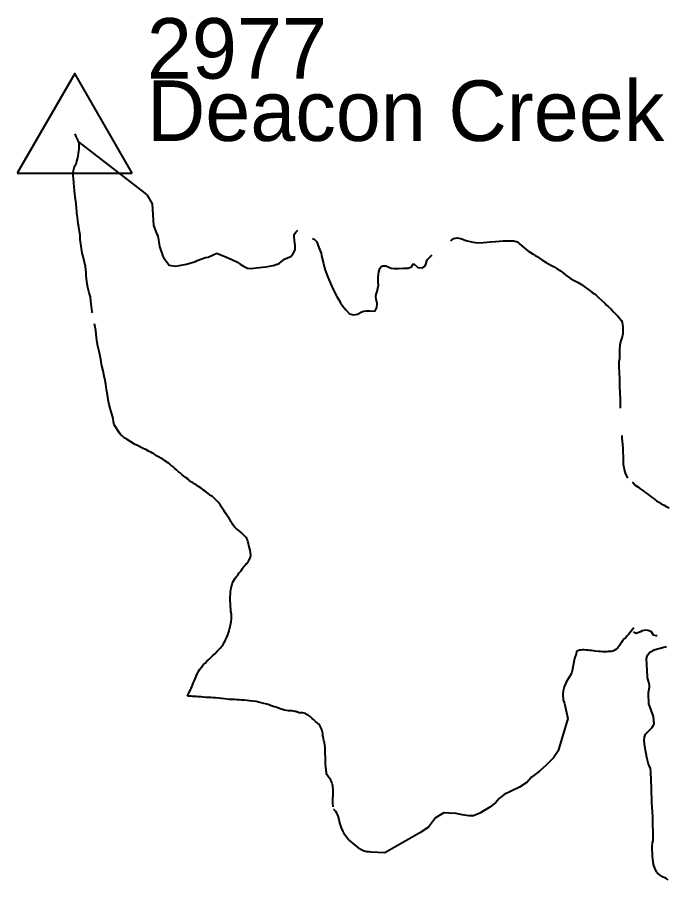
# Model space of a CAD drawing. Extents: x 322505 to 642419, y 5806860 to 5919753.
# Drawn here: x 548630 to 552397, y 5870230 to 5875217 of the extents above; entities that cross this region are included whole.
import ezdxf

# ---------------------------------------------------------------- set-up
doc = ezdxf.new("R2010")
doc.units = 0
doc.header["$LTSCALE"] = 140
doc.layers.add('1', color=7, linetype='Continuous', lineweight=40)
doc.layers.add('5', color=7, linetype='Continuous', lineweight=40)

msp = doc.modelspace()

# ---------------------------------------------------------------- linework, layer by layer
at = {"layer": '1'}
msp.add_line((548630.1, 5874315.4), (549295.5, 5874315.4), dxfattribs=at)
msp.add_lwpolyline([(549295.5, 5874315.4), (548962.8, 5874891.6), (548630.1, 5874315.4)], dxfattribs=at)
at = {"layer": '5'}
msp.add_line((548987, 5874494), (549368, 5874199), dxfattribs=at)
for points in [[(548960, 5874242), (548958, 5874254), (548957, 5874266), (548955, 5874283), (548954, 5874301), (548954, 5874317), (548955, 5874331), (548959, 5874346), (548963, 5874357), (548968, 5874366), (548972, 5874374), (548975, 5874385), (548978, 5874399), (548982, 5874414), (548985, 5874429), (548987, 5874443), (548988, 5874456), (548989, 5874470), (548989, 5874484), (548987, 5874494), (548981, 5874506), (548980, 5874509), (548974, 5874520), (548971, 5874527), (548965, 5874542)], [(548974, 5874094), (548973, 5874111), (548970, 5874140), (548967, 5874166), (548964, 5874194), (548962, 5874216), (548960, 5874238), (548960, 5874242)], [(549368, 5874199), (549382, 5874189), (549411, 5874139), (549418, 5874013), (549437, 5873962), (549443, 5873953), (549453, 5873891), (549471, 5873836), (549475, 5873828), (549509, 5873784), (549545, 5873777), (549608, 5873789), (549660, 5873805), (549670, 5873810), (549719, 5873827), (549734, 5873829), (549785, 5873852)], [(549065, 5873507), (549064, 5873513), (549060, 5873545), (549056, 5873576), (549053, 5873600), (549046, 5873624), (549038, 5873655), (549032, 5873688), (549030, 5873707), (549029, 5873724), (549028, 5873742), (549024, 5873776), (549018, 5873809), (549011, 5873833), (549006, 5873853), (549001, 5873879), (548997, 5873907), (548994, 5873932), (548993, 5873956), (548990, 5873979), (548987, 5874003), (548983, 5874025), (548980, 5874042), (548978, 5874061), (548975, 5874085), (548974, 5874094)], [(549785, 5873852), (549801, 5873845), (549817, 5873839), (549841, 5873829), (549871, 5873816), (549899, 5873802), (549919, 5873790), (549938, 5873777), (549961, 5873767), (549985, 5873765), (550012, 5873768), (550067, 5873773), (550110, 5873782), (550127, 5873787), (550144, 5873794), (550159, 5873805), (550176, 5873818), (550197, 5873827), (550212, 5873834), (550226, 5873850), (550237, 5873872), (550238, 5873896), (550233, 5873928), (550231, 5873948), (550232, 5873961), (550241, 5873975), (550253, 5873986)], [(551137, 5873925), (551141, 5873928), (551154, 5873938), (551173, 5873941), (551201, 5873936), (551223, 5873927), (551256, 5873918), (551292, 5873913), (551327, 5873914), (551367, 5873918), (551395, 5873921), (551419, 5873923), (551439, 5873924), (551463, 5873925), (551483, 5873925), (551501, 5873924), (551506, 5873923), (551516, 5873921)], [(550338, 5873938), (550347, 5873933), (550362, 5873918), (550371, 5873895), (550382, 5873867), (550387, 5873852), (550390, 5873837), (550400, 5873794), (550409, 5873761), (550422, 5873724), (550441, 5873677), (550459, 5873638), (550478, 5873603), (550489, 5873584), (550500, 5873566), (550513, 5873547), (550530, 5873525), (550551, 5873503), (550575, 5873496), (550597, 5873501), (550613, 5873508), (550619, 5873511), (550629, 5873516), (550632, 5873517), (550635, 5873517), (550651, 5873519), (550668, 5873520), (550689, 5873517), (550700, 5873519), (550704, 5873527), (550709, 5873538), (550711, 5873562), (550706, 5873586), (550704, 5873603), (550706, 5873616), (550711, 5873631), (550716, 5873651), (550718, 5873668), (550717, 5873685), (550717, 5873710), (550718, 5873729), (550720, 5873745), (550727, 5873765), (550734, 5873775), (550744, 5873780), (550762, 5873779), (550778, 5873771), (550792, 5873767), (550809, 5873765), (550835, 5873765), (550862, 5873766), (550891, 5873767), (550910, 5873774), (550919, 5873790), (550921, 5873794)], [(551516, 5873921), (551520, 5873918), (551534, 5873906), (551559, 5873886), (551583, 5873867), (551613, 5873848), (551625, 5873840), (551637, 5873833), (551645, 5873828), (551663, 5873815), (551689, 5873799), (551715, 5873783), (551734, 5873773), (551752, 5873762), (551771, 5873750), (551788, 5873737), (551803, 5873725), (551815, 5873716), (551830, 5873707), (551851, 5873695), (551873, 5873684), (551892, 5873672), (551909, 5873660), (551929, 5873645), (551943, 5873635), (551955, 5873626), (551965, 5873620), (551977, 5873610), (551992, 5873596), (552008, 5873581), (552027, 5873564), (552038, 5873553)], [(550921, 5873794), (550947, 5873770), (550970, 5873768), (550986, 5873778), (550994, 5873791), (550995, 5873794), (550995, 5873796), (551001, 5873815), (551019, 5873833), (551029, 5873841)], [(552038, 5873553), (552045, 5873547), (552064, 5873529), (552078, 5873514), (552092, 5873500), (552102, 5873489), (552115, 5873475), (552123, 5873466)], [(549223, 5872810), (549191, 5872860), (549187, 5872877), (549184, 5872897), (549177, 5872923), (549169, 5872949), (549162, 5872977), (549156, 5873004), (549151, 5873033), (549146, 5873065), (549142, 5873095), (549138, 5873117), (549133, 5873141), (549126, 5873173), (549118, 5873209), (549115, 5873225), (549113, 5873239), (549109, 5873257), (549103, 5873285), (549097, 5873315), (549093, 5873337), (549089, 5873366), (549084, 5873406), (549077, 5873445)], [(552123, 5873466), (552124, 5873463), (552128, 5873452), (552130, 5873440), (552131, 5873426), (552132, 5873413), (552132, 5873404), (552132, 5873397), (552131, 5873387), (552130, 5873376), (552125, 5873357), (552119, 5873340), (552114, 5873321), (552112, 5873297), (552112, 5873274), (552113, 5873255), (552112, 5873242), (552109, 5873224), (552108, 5873206), (552109, 5873188), (552110, 5873171), (552110, 5873169)], [(552110, 5873169), (552111, 5873152), (552112, 5873135), (552112, 5873120), (552112, 5873108), (552112, 5873094), (552113, 5873074), (552114, 5873053), (552115, 5873036), (552116, 5873021), (552116, 5873007), (552117, 5872995), (552117, 5872956)], [(549643, 5872527), (549636, 5872531), (549625, 5872539), (549622, 5872542), (549618, 5872544), (549615, 5872547), (549611, 5872551), (549606, 5872554), (549594, 5872564), (549582, 5872573), (549572, 5872582), (549561, 5872591), (549550, 5872600), (549540, 5872609), (549529, 5872619), (549518, 5872628), (549508, 5872637), (549499, 5872643), (549491, 5872649), (549482, 5872654), (549471, 5872661), (549460, 5872668), (549447, 5872675), (549439, 5872680), (549432, 5872685), (549426, 5872689), (549419, 5872693), (549413, 5872697), (549403, 5872702), (549393, 5872707), (549383, 5872712), (549373, 5872717), (549365, 5872720), (549347, 5872729), (549329, 5872738), (549309, 5872749), (549286, 5872762), (549260, 5872779), (549249, 5872786), (549241, 5872793), (549234, 5872799), (549228, 5872804), (549223, 5872810)], [(552126, 5872798), (552126, 5872784), (552128, 5872766), (552130, 5872747), (552131, 5872725), (552132, 5872700), (552133, 5872680), (552133, 5872661), (552133, 5872646), (552134, 5872633), (552135, 5872624), (552137, 5872615), (552140, 5872603), (552144, 5872589), (552148, 5872575), (552154, 5872562), (552160, 5872553)], [(549860, 5871685), (549860, 5871687), (549862, 5871694), (549864, 5871703), (549866, 5871712), (549867, 5871722), (549869, 5871738), (549869, 5871753), (549868, 5871767), (549866, 5871781), (549865, 5871795), (549864, 5871811), (549863, 5871827), (549862, 5871842), (549862, 5871856), (549862, 5871868), (549863, 5871880), (549864, 5871893), (549866, 5871908), (549869, 5871924), (549873, 5871941), (549878, 5871954), (549884, 5871965), (549890, 5871974), (549897, 5871983), (549905, 5871992), (549914, 5872004), (549924, 5872017), (549933, 5872030), (549941, 5872041), (549948, 5872049), (549952, 5872054), (549957, 5872059), (549962, 5872065), (549967, 5872072), (549972, 5872079), (549978, 5872093), (549980, 5872107), (549979, 5872121), (549976, 5872135), (549973, 5872150), (549970, 5872162), (549967, 5872174), (549964, 5872185), (549961, 5872195), (549957, 5872203), (549953, 5872209), (549947, 5872216), (549940, 5872223), (549932, 5872231), (549924, 5872238), (549913, 5872247), (549903, 5872256), (549894, 5872263), (549886, 5872271), (549878, 5872281), (549875, 5872286), (549872, 5872291), (549869, 5872296), (549866, 5872301), (549864, 5872306), (549858, 5872316), (549850, 5872327), (549842, 5872338), (549834, 5872350), (549824, 5872365), (549819, 5872372), (549815, 5872379), (549812, 5872384), (549808, 5872390), (549805, 5872395), (549799, 5872404), (549792, 5872413), (549784, 5872421), (549777, 5872429), (549770, 5872435), (549765, 5872440), (549759, 5872445), (549751, 5872450), (549744, 5872456), (549735, 5872463), (549725, 5872471), (549717, 5872477), (549708, 5872483), (549701, 5872489), (549693, 5872495), (549679, 5872503), (549664, 5872513), (549649, 5872522), (549643, 5872527)], [(552186, 5872528), (552191, 5872524), (552204, 5872512), (552218, 5872501), (552230, 5872492), (552241, 5872484), (552250, 5872478), (552256, 5872474), (552265, 5872467), (552276, 5872460), (552286, 5872452), (552296, 5872444), (552307, 5872436), (552317, 5872429), (552327, 5872421), (552339, 5872414), (552354, 5872404), (552371, 5872395), (552386, 5872387), (552400, 5872380)], [(549615, 5871292), (549617, 5871297), (549622, 5871308), (549627, 5871318), (549631, 5871328), (549635, 5871336), (549639, 5871345), (549643, 5871355), (549648, 5871366), (549653, 5871378), (549658, 5871391), (549664, 5871405), (549669, 5871416), (549674, 5871427), (549680, 5871437), (549686, 5871447), (549695, 5871459), (549706, 5871472), (549717, 5871483), (549727, 5871494), (549737, 5871503), (549748, 5871513), (549760, 5871524), (549773, 5871537), (549787, 5871552), (549803, 5871569), (549813, 5871580), (549821, 5871591), (549827, 5871601), (549832, 5871611), (549837, 5871622), (549842, 5871633), (549847, 5871646), (549852, 5871658), (549855, 5871669), (549858, 5871680), (549860, 5871685)], [(552195.1, 5871686.7), (552188, 5871677), (552180, 5871667), (552172.9, 5871656.9), (552164.6, 5871647.6), (552156.5, 5871639.5), (552148.5, 5871631.5), (552139.6, 5871622.5), (552129.9, 5871611.9), (552123.2, 5871602.3), (552117.2, 5871592.3), (552112.2, 5871585.2), (552107.1, 5871577.2), (552100.6, 5871568.4), (552091.9, 5871561.9), (552082.3, 5871555.5), (552073.5, 5871552.2), (552064.9, 5871550.1), (552055.3, 5871549), (552047.3, 5871549), (552039.3, 5871548), (552028, 5871548), (552014.8, 5871548), (552002.8, 5871549), (551990.7, 5871549), (551972.2, 5871551.1), (551962.1, 5871553.1), (551951.3, 5871555), (551940.4, 5871556), (551928.6, 5871558), (551918.8, 5871558), (551907.8, 5871559), (551898.3, 5871559), (551889.6, 5871558), (551882, 5871557.1), (551872.5, 5871554.2), (551863, 5871551.1)], [(552294.8, 5871664.8), (552294.2, 5871664.5), (552275.8, 5871672.1), (552264.4, 5871673), (552243.7, 5871668.3), (552233.9, 5871663.4), (552208.8, 5871654.6), (552194.1, 5871661.1)], [(552330.1, 5871640.7), (552324.6, 5871639.9), (552308.9, 5871644.7), (552294.8, 5871664.8)], [(551863, 5871551.1), (551863, 5871548.8), (551861.9, 5871536.9), (551851.8, 5871509.7), (551836.8, 5871428.3), (551825.3, 5871406.5), (551805.4, 5871375.6), (551791.7, 5871346.3), (551786, 5871322.3), (551785, 5871301), (551786, 5871270), (551793.8, 5871248.4), (551814.5, 5871161.6)], [(552393, 5870230), (552389, 5870234), (552382, 5870238), (552358, 5870248), (552333, 5870268), (552327, 5870276), (552316, 5870297), (552309, 5870319), (552303, 5870366), (552301, 5870420), (552304, 5870444), (552307, 5870456), (552308, 5870499), (552306, 5870556), (552306, 5870596), (552300, 5870677), (552298, 5870758), (552293, 5870854), (552291, 5870873), (552280, 5870899), (552270, 5870936), (552259, 5871001), (552256, 5871036), (552257, 5871055), (552262, 5871071), (552299, 5871109), (552310, 5871123), (552313, 5871131), (552310, 5871173), (552282, 5871247), (552280, 5871304), (552280, 5871313), (552286, 5871344), (552286, 5871353), (552283, 5871372), (552275, 5871397), (552274, 5871405), (552269, 5871510), (552275, 5871529), (552288, 5871545), (552296, 5871550), (552313, 5871559), (552333, 5871566), (552384, 5871579)], [(550140, 5871223), (550127, 5871227), (550116, 5871230), (550106, 5871233), (550098, 5871236), (550094, 5871238), (550087, 5871241), (550073, 5871246), (550055, 5871250), (550033, 5871255), (550011, 5871260), (549991, 5871263), (549974, 5871265), (549959, 5871267), (549943, 5871268), (549926, 5871269), (549913, 5871270), (549900, 5871271), (549887, 5871272), (549876, 5871272), (549868, 5871273), (549858, 5871273), (549844, 5871275), (549828, 5871276), (549811, 5871278), (549793, 5871280), (549777, 5871281), (549763, 5871282), (549750, 5871283), (549736, 5871284), (549722, 5871284), (549707, 5871285), (549693, 5871287), (549679, 5871287), (549667, 5871289), (549658, 5871289), (549652, 5871289), (549645, 5871290), (549636, 5871291), (549626, 5871291), (549615, 5871292)], [(550386, 5871110), (550386, 5871111), (550382, 5871118), (550378, 5871124), (550373, 5871129), (550369, 5871133), (550364, 5871137), (550357, 5871143), (550350, 5871149), (550343, 5871156), (550336, 5871163), (550329, 5871169), (550324, 5871173), (550319, 5871178), (550313, 5871182), (550305, 5871186), (550297, 5871191), (550289, 5871193), (550281, 5871195), (550274, 5871196), (550267, 5871196), (550261, 5871196), (550255, 5871198), (550250, 5871199), (550245, 5871201), (550240, 5871202), (550235, 5871203), (550227, 5871205), (550219, 5871206), (550210, 5871207), (550199, 5871207), (550187, 5871209), (550175, 5871211), (550164, 5871215), (550156, 5871217), (550147, 5871220), (550140, 5871223)], [(551814.5, 5871161.6), (551757.9, 5870975.6), (551731.4, 5870935.8), (551689.2, 5870893.1), (551649.1, 5870857), (551604.5, 5870824), (551577.7, 5870794.9), (551535.1, 5870764.9), (551486.5, 5870741.6), (551445.1, 5870723.7), (551416.3, 5870699.7), (551394.7, 5870675), (551362.8, 5870650), (551304.9, 5870614.1), (551268.1, 5870598.8), (551240.7, 5870599.6), (551202.6, 5870605.6), (551168.1, 5870612.1), (551127.4, 5870615.1), (551097, 5870617), (551048.3, 5870587.1), (551009, 5870534.2), (550957.7, 5870501.3), (550755, 5870384.8)], [(550418, 5870850), (550418, 5870851), (550417, 5870859), (550416, 5870868), (550415, 5870878), (550414, 5870887), (550413, 5870895), (550413, 5870902), (550413, 5870909), (550413, 5870916), (550413, 5870929), (550412, 5870943), (550411, 5870957), (550410, 5870970), (550410, 5870982), (550410, 5870987), (550410, 5870992), (550410, 5870997), (550409, 5871004), (550409, 5871010), (550407, 5871018), (550406, 5871025), (550404, 5871030), (550402, 5871036), (550401, 5871042), (550400, 5871049), (550399, 5871056), (550398, 5871063), (550398, 5871070), (550397, 5871076), (550396, 5871083), (550394, 5871089), (550392, 5871096), (550389, 5871103), (550386, 5871110)], [(550457.2, 5870651.3), (550457, 5870653), (550457, 5870654), (550457, 5870656), (550456, 5870657), (550455, 5870669), (550454, 5870682), (550454, 5870694), (550455, 5870706), (550456, 5870715), (550457, 5870723), (550457, 5870732), (550457, 5870742), (550456, 5870753), (550455, 5870765), (550454, 5870776), (550452, 5870785), (550450, 5870793), (550446, 5870801), (550441, 5870809), (550437, 5870815), (550432, 5870821), (550428, 5870827), (550424, 5870832), (550421, 5870838), (550419, 5870844), (550418, 5870850)], [(550755, 5870384.8), (550676.5, 5870390), (550663.6, 5870392), (550653.8, 5870392), (550642.9, 5870393.1), (550630.9, 5870397.4), (550616.3, 5870405.8), (550603, 5870415), (550587.8, 5870427.1), (550570.8, 5870441.2), (550556.6, 5870453.3), (550544.4, 5870465.5), (550534.1, 5870476.9), (550524.7, 5870490.4), (550514.5, 5870509.8), (550505.4, 5870530.1), (550497.2, 5870552.5), (550491.1, 5870573.8), (550487.2, 5870593.6), (550483.4, 5870604.1), (550478.6, 5870614.5), (550472.2, 5870623.8), (550470.2, 5870625.7), (550467.4, 5870629.5), (550461.8, 5870634.2), (550458.4, 5870637.1)]]:
    msp.add_lwpolyline(points, dxfattribs=at)

# ---------------------------------------------------------------- texts
at = {"layer": '1'}
for s, p in [('2977', (549379.6, 5874861.7)), ('Deacon Creek', (549379.6, 5874501.7))]:
    msp.add_text(s, height=350, dxfattribs=at).set_placement(p)

doc.saveas('drawing.dxf')
